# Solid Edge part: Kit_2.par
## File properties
Username: bmolnar
Dokumentum tartalom típus: 0
Author: bmolnar
Last saved by: bmolnar
Revision: 77
Sűrűség: 0,000 kg/m^3
Pontosság: 0,990
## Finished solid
Body 1: solid body, 13 faces, 18 edges, 14 vertices, 2 separate solids.
  Faces by surface: plane 7, cylinder 4, cone 1, torus 1
  Edges by curve: circle 10, line 8
Bounding box of the edges (mm; curved faces can reach further): 19.000 x 18.450 x 3.100, from (-9.5, -9.5, 0.3) to (9.5, 8.95, 3.4).
Cylindrical faces by radius (mm): R7 x1, R8.5 x1, R8.95 x1, R9.5 x1
Conical faces (half-angle, radius in mm at the cone's reference point): 45 deg R6.75 x1
Toroidal faces (ring radius, tube radius in mm): R7.4 r0.4 x1
Planar faces by outward normal: +z 2, -z 3, oblique 2
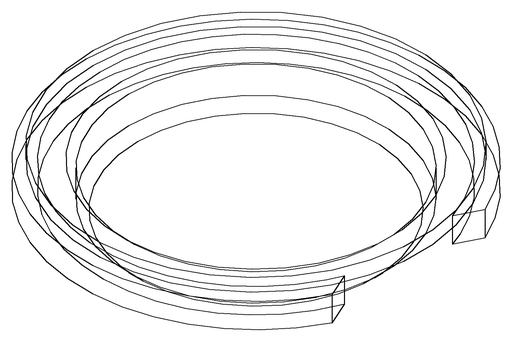
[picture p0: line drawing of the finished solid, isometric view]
